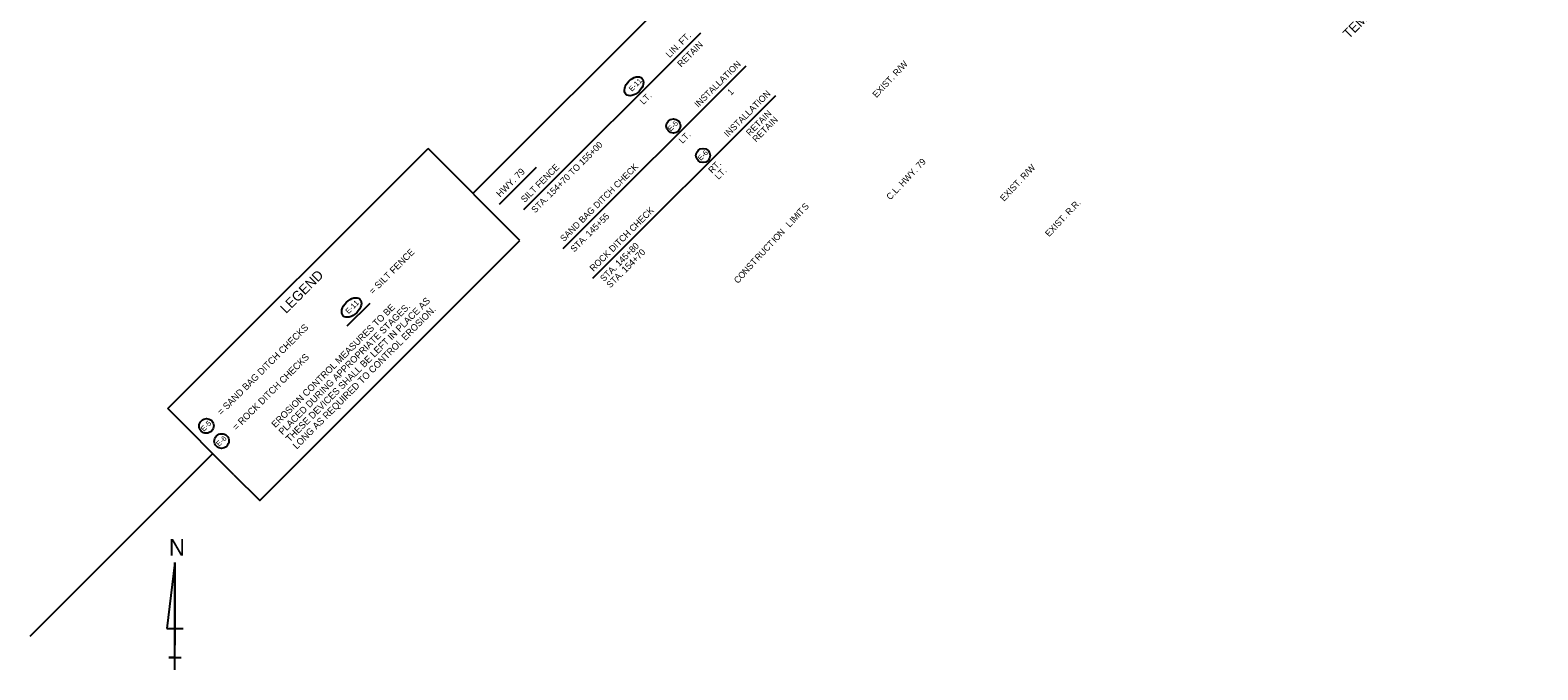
# Model space of a CAD drawing. Extents: x 1377476 to 1378879, y 1932630 to 1934097.
# Drawn here: x 1377476 to 1378879, y 1932630 to 1933226 of the extents above; entities that cross this region are included whole.
import ezdxf

# ---------------------------------------------------------------- set-up
doc = ezdxf.new("R2010")
doc.units = 0
for name, color, linetype in [('1', 7, 'Continuous'), ('44', 7, 'Continuous'), ('60', 7, 'Continuous'), ('63', 7, 'Continuous'), ('Level 1', 7, 'Continuous'), ('Level 44', 7, 'Continuous'), ('R_Draft', 7, 'Continuous')]:
    doc.layers.add(name, color=color, linetype=linetype)

msp = doc.modelspace()

# ---------------------------------------------------------------- linework, layer by layer
at = {"layer": '1'}
for p, q in [((1377887.9, 1933073.8), (1378090.3, 1933276.1)), ((1377603.7, 1932873.4), (1377846, 1933115.7)), ((1377931.6, 1933030.1), (1377846, 1933115.7)), ((1377665.3, 1932811.8), (1377603.7, 1932873.4)), ((1377475.5, 1932661.4), (1377645.6, 1932831.5))]:
    msp.add_line(p, q, dxfattribs=at)
msp.add_lwpolyline([(1377665.3, 1932811.8), (1377689.3, 1932787.8), (1377931.6, 1933030.1)], dxfattribs=at)
for centre in [(1378074.5, 1933136.7), (1378102.1, 1933109.2)]:
    msp.add_circle(centre, 6.61, dxfattribs=at)
msp.add_ellipse((1378037.8, 1933173.7), major_axis=(7.44, 7.44), ratio=0.638788, dxfattribs=at)
at = {"layer": '44'}
for p, q in [((1377935.3, 1933058.9), (1378099.9, 1933223.5)), ((1377971.8, 1933022.4), (1378142.2, 1933192.8)), ((1377999.4, 1932994.8), (1378169.8, 1933165.2)), ((1377912.5, 1933063.8), (1377947, 1933098.3))]:
    msp.add_line(p, q, dxfattribs=at)
at = {"layer": '63'}
for p, q in [((1377610.4, 1932730.1), (1377602.8, 1932668.5)), ((1377610.4, 1932630.1), (1377610.4, 1932730.1)), ((1377610.4, 1932730.1), (1377610.4, 1932653.1)), ((1377602.8, 1932668.5), (1377618.1, 1932668.5)), ((1377610.4, 1932630.1), (1377610.4, 1932653.1)), ((1377610.4, 1932641.6), (1377604.7, 1932641.6)), ((1377604.7, 1932641.6), (1377616.2, 1932641.6)), ((1377610.4, 1932630.1), (1377610.4, 1932641.6))]:
    msp.add_line(p, q, dxfattribs=at)
at = {"layer": 'Level 1'}
for centre, major_axis, ratio in [((1377774.8, 1932967.6), (7.75, 7.75), 0.622952), ((1377639.7, 1932857.3), (-4.87, -4.86), 0.97521), ((1377653.8, 1932843.2), (-4.87, -4.86), 0.97521)]:
    msp.add_ellipse(centre, major_axis=major_axis, ratio=ratio, dxfattribs=at)
at = {"layer": 'Level 44'}
msp.add_lwpolyline([(1377770.8, 1932950.4), (1377792.1, 1932971.7)], dxfattribs=at)

# ---------------------------------------------------------------- texts
at = {"layer": '1'}
for s, p in [('E-11', (1378035.8, 1933168.4)), ('E-5 ', (1378072.1, 1933131.4)), ('E-6 ', (1378099.9, 1933104))]:
    msp.add_text(s, height=4.8, rotation=45, dxfattribs=at).set_placement(p)
at = {"layer": '44'}
for s, height, p in [('LIN. FT.', 6, (1378071, 1933199.9)), ('RETAIN', 6, (1378081.7, 1933191.1)), ('INSTALLATION', 6, (1378097.6, 1933153.5)), ('LT.', 6, (1378046.6, 1933156.2)), ('INSTALLATION', 6, (1378125.2, 1933125.9)), ('1', 6, (1378128.2, 1933164.7)), ('RETAIN', 6, (1378145.7, 1933127)), ('RETAIN', 6, (1378151.6, 1933121.1)), ('LT.', 6, (1378083, 1933119.8)), ('STA. 154+70 TO 155+00', 6, (1377945.8, 1933055.2)), ('SILT FENCE      ', 6, (1377936, 1933064.9)), ('SAND BAG DITCH CHECK', 6, (1377972.6, 1933028.4)), ('RT.', 6, (1378110.5, 1933092.1)), ('HWY. 79', 6.25, (1377913.2, 1933069.9)), ('LT.', 6, (1378116.5, 1933086.3)), ('ROCK DITCH CHECK', 6, (1378000.1, 1933000.8)), ('STA. 145+55', 6, (1377982.2, 1933018.7)), ('STA. 145+80', 6, (1378009.8, 1932991.2)), ('STA. 154+70', 6, (1378015.7, 1932985.3))]:
    msp.add_text(s, height=height, rotation=45, dxfattribs=at).set_placement(p)
at = {"layer": '60'}
msp.add_text('TEMPORARY EROSION CONTROL DETAILS', height=9, rotation=45, dxfattribs=at).set_placement((1378703.4, 1933217.4))
at = {"layer": '63'}
msp.add_text('N', height=15.4, rotation=360, dxfattribs=at).set_placement((1377604.8, 1932736.5))
at = {"layer": 'Level 1'}
for s, height, p in [('= SILT FENCE', 6.25, (1377794.8, 1932979.4)), ('THESE DEVICES SHALL BE LEFT IN PLACE AS ', 6.25, (1377717.2, 1932841.9)), ('EROSION CONTROL MEASURES TO BE', 6.25, (1377703.9, 1932855.2)), ('PLACED DURING APPROPRIATE STAGES. ', 6.25, (1377710.5, 1932848.5)), ('LONG AS REQUIRED TO CONTROL EROSION.', 6.25, (1377723.8, 1932835.2)), ('E-11 ', 4.88, (1377772, 1932961.4)), ('= SAND BAG DITCH CHECKS', 6.25, (1377653.6, 1932866.8)), ('= ROCK DITCH CHECKS', 6.25, (1377667.7, 1932852.7)), ('E-5 ', 4.88, (1377637.3, 1932851.8)), ('E-6 ', 4.88, (1377651.5, 1932837.8))]:
    msp.add_text(s, height=height, rotation=45, dxfattribs=at).set_placement(p)
at = {"layer": 'Level 44'}
msp.add_text('LEGEND', height=9.14, rotation=45, dxfattribs=at).set_placement((1377713.9, 1932961.4))
at = {"layer": 'R_Draft'}
for s, rotation, p in [('EXIST. R/W', 46.6607, (1378263.6, 1933162.5)), ('C.L. HWY. 79', 46.6607, (1378276.5, 1933067.3)), ('EXIST. R/W', 46.6607, (1378382.4, 1933066)), ('T', 46.9549, (1378193.6, 1933053.3)), ('S', 46.9549, (1378197.6, 1933057.6)), ('EXIST. R.R.', 46.6607, (1378424.3, 1933033)), ('L', 47.0791, (1378182.9, 1933041.8)), ('I', 46.9981, (1378186.6, 1933045.7)), ('M', 46.9981, (1378187.9, 1933047.2)), ('I', 46.9549, (1378192.3, 1933051.9)), ('I', 46.9593, (1378169.6, 1933027.5)), ('O', 47.0517, (1378170.9, 1933029)), ('N', 47.0517, (1378174.9, 1933033.3)), ('R', 46.9386, (1378153.9, 1933010.7)), ('U', 47.0798, (1378157.8, 1933014.9)), ('C', 47.0798, (1378161.7, 1933019.1)), ('T', 46.9593, (1378165.6, 1933023.2)), ('N', 48.7715, (1378142.3, 1932998)), ('S', 47.0834, (1378146.1, 1933002.3)), ('T', 47.0834, (1378149.9, 1933006.4)), ('C', 48.5931, (1378134.7, 1932989.4)), ('O', 48.7715, (1378138.5, 1932993.6))]:
    msp.add_text(s, height=6, rotation=rotation, dxfattribs=at).set_placement(p)

doc.saveas('drawing.dxf')
